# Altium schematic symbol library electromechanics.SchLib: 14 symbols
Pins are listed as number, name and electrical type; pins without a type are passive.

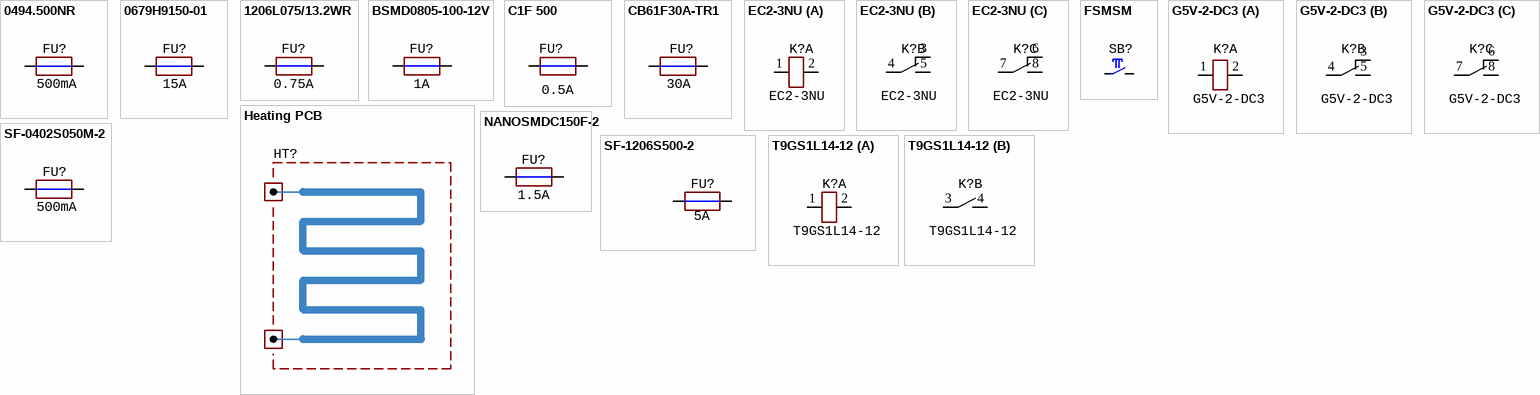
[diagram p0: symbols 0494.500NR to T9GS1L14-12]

## 0494.500NR
designator FU?  value 500mA  (hidden comment: 0494.500NR)
Fuse, 0.5A, 32VDC, 187 mOhms, 0603, Slow, -55...125°C; Manufacturer: Littelfuse
footprint FUSE: 0603
pins: 1, 2

## 0679H9150-01
designator FU?  value 15A  (hidden comment: 0679H9150-01)
Fuse, 15A, 60VDC, 350VAC, 3.8 mOhms, -55...125°C; Manufacturer: BelFuse; Manufacturer: Bel
footprint FUSE: 0679H (BelFuse)
pins: 1, 2

## 1206L075/13.2WR
designator FU?  value 0.75A  (hidden comment: 1206L075/13.2WR)
Fuse, 0.75A, 13.2VDC, 360 mOhms, 1206, Slow, -40...+85°C; Manufacturer: Littelfuse
footprint RES: 1206
pins: 1, 2

## BSMD0805-100-12V
designator FU?  value 1A  (hidden comment: BSMD0805-100-12V)
Fuse, 1A, 12VDC, 40 mOhms, 0805, Resettable, -40...+85°C; Manufacturer: BHFUSE
footprint FUSE: 0805
pins: 1, 2

## C1F 500
designator FU?  value 0.5A  (hidden comment: C1F 500)
Fuse, 0.5A, 63VDC, 870 mOhms, 1206, Fast, -55...+125°C; Manufacturer: BelFuse; Manufacturer: Bel TRP; Manufacturer Part Number: C1F500
footprint RES: 1206
pins: 1, 2

## CB61F30A-TR1
designator FU?  value 30A  (hidden comment: CB61F30A-TR1)
Fuse, 30A, 72VDC, case 6125, 1.2 mOhms, -55...125°C; Manufacturer: BelFuse; Manufacturer: Eaton
footprint FUSE: 6125 (2410)
pins: 1, 2

## EC2-3NU
designator K?
Relay, 2 x NO/NC, 2A, signal 3VDC, -40...+85°C; Manufacture: Kemet; Parameter 1: series EC2
footprint REL: EC2-3NU
part A pins: 1, 2
part B pins: 3, 4, 5
part C pins: 6, 7, 8

## FSMSM
designator SB?  (value not drawn)
Button, 6x3.5 mm, 12VDC, 50mA; Manufacturer: TE Connectivity
footprint BUT: 6x3.5 SMD
pins: 1, 2

## G5V-2-DC3
designator K?
Relay, 2 x NO/NC, 2A, signal 3VDC, -40...+85°C; Manufacture: Omron
footprint REL: OMRON_G5V (Omron G5V relay)
part A pins: 1, 2
part B pins: 3, 4, 5
part C pins: 6, 7, 8

## Heating PCB
designator HT?  (value not drawn)  (no BOM)
footprint PCB: Heating
pins: 1 IN, 2 IN

## NANOSMDC150F-2
designator FU?  value 1.5A  (hidden comment: NANOSMDC150F-2)
Fuse, 1.5A, 6VDC, 110 mOhms, 1206, Slow, -40...+85°C; Manufacturer: Littelfuse
footprint RES: 1206
pins: 1, 2

## SF-0402S050M-2
designator FU?  value 500mA  (hidden comment: SF-0402S050M-2)
Fuse, 0.5A, 24VDC, 380 mOhms, 0402, Slow, -55...125°C; Manufacturer: Bourns
footprint RES: 0402
pins: 1, 2

## SF-1206S500-2
designator FU?  value 5A  (hidden comment: SF-1206S500-2)
Fuse, 5A, 24VDC, 13 mOhms, 1206, Slow, -20...120°C; Manufacturer: Bourns
footprint RES: 1206
pins: 1, 2

## T9GS1L14-12
designator K?
Relay, 480VAC, 30A, signal 12VDC, 1 x NO, -40...+85°C; Manufacture: TE
footprint REL: T9GS1
part A pins: 1, 2
part B pins: 3, 4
